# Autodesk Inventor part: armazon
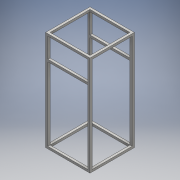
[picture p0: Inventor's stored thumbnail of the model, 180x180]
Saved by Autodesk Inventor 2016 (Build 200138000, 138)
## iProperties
Created: 2016-06
Part Number: armazon
Material: Genérico
Document SubType Name: Modeling
Designer: adm
Density: 1 g/cm^3
Appearance: Valor por defecto
Author: adm
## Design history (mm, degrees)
node "Boceto 3D1"
sketch "Boceto1"
  geometry: L1 (-100, -50)-(-90, -50); L2 (-90, -50)-(-90, -40); L3 (-90, -40)-(-100, -40); L4 (-100, -40)-(-100, -50); L5 (-100, 140)-(-90, 140); L6 (-90, 140)-(-90, 150); L7 (-90, 150)-(-100, 150); L8 (-100, 150)-(-100, 140); L9 (90, 140)-(100, 140); L10 (100, 140)-(100, 150); L11 (100, 150)-(90, 150); L12 (90, 150)-(90, 140); L13 (100, -50)-(100, -40); L14 (90, -50)-(100, -50); L15 (100, -40)-(90, -40); L16 (90, -40)-(90, -50); L17 (-100, -50)-(100, -50); L18 (100, -50)-(100, 150); L19 (100, 150)-(-100, 150); L20 (-100, 150)-(-100, -50); 1 further point
  constraints: 40 end point, 10 parallel, 5 horizontal, 5 perpendicular
  dimensions: "d2" = 10 distance of L3.end L2.end; "d3" = 10 distance of L2.end L1.end; "d4" = 10 distance of L7.end L6.end; "d5" = 10 distance of L6.end L5.end; "d6" = 10 distance of L11.end L10.end; "d7" = 10 distance of L10.end L9.end; "d8" = 10 distance of L15.end L13.end; "d9" = 10 distance of L13.end L13.start; "d47" = 200 distance of L19.end L1.start
extrude "Extrusión1" new body sketch "Boceto1" distance "d10" = 450; taper "d11" = 0 deg
sketch "Boceto2"
  geometry: L1 (0, 0)-(-450, 0) reference; L2 (0, 0)-(-10, 0); L3 (-10, 0)-(-10, 10); L4 (-10, 10)-(0, 10); L5 (0, 10)-(0, 0); 1 further point
  constraints: 8 end point, 2 parallel, 1 horizontal, 1 perpendicular
  dimensions: "d12" = 10 distance of L3.end L4.end; "d13" = 10 distance of L2.end L3.end
extrude "Extrusión2" join sketch "Boceto2" distance "d14" = 180; taper "d15" = 0 deg
sketch "Boceto3"
  geometry: L1 (0, 0)-(-10, 0); L2 (-10, 0)-(-10, 10); L3 (-10, 10)-(0, 10); L4 (0, 10)-(0, 0); 1 further point
  constraints: 8 end point, 2 parallel, 1 horizontal, 1 perpendicular
  dimensions: "d16" = 10 distance of L2.end L3.end; "d17" = 10 distance of L1.end L2.end
extrude "Extrusión3" join sketch "Boceto3" distance "d18" = 180; taper "d19" = 0 deg
sketch "Boceto4"
  geometry: L1 (440, 0)-(0, 0) reference; L2 (0, 0)-(10, 0); L3 (10, 0)-(10, 10); L4 (10, 10)-(0, 10); L5 (0, 10)-(0, 0); L6 (440, 190)-(0, 190) reference; L7 (0, 190)-(10, 190); L8 (10, 190)-(10, 200); L9 (10, 200)-(0, 200); L10 (0, 200)-(0, 190); 1 further point
  constraints: 16 end point, 4 parallel, 2 horizontal, 2 perpendicular
  dimensions: "d20" = 10 distance of L4.end L3.end; "d21" = 10 distance of L3.end L2.end; "d22" = 10 distance of L9.end L8.end; "d23" = 10 distance of L8.end L7.end
extrude "Extrusión4" join sketch "Boceto4" distance "d24" = 180; taper "d25" = 0 deg
sketch "Boceto5"
  geometry: L1 (200, -450)-(200, 0) reference; L2 (10, -440)-(190, -440) reference; L3 (200, -450)-(190, -450); L4 (190, -450)-(190, -440); L5 (190, -440)-(200, -440); L6 (200, -440)-(200, -450); 1 further point
  constraints: 8 end point, 2 parallel, 1 horizontal, 1 perpendicular
  dimensions: "d26" = 10 distance of L2.end L5.end (derived); "d27" = 10 distance of L3.end L2.end (derived)
extrude "Extrusión5" join sketch "Boceto5" distance "d28" = 180; taper "d29" = 0 deg
sketch "Boceto6"
  geometry: L1 (10, -440)-(190, -440) reference; L2 (0, -450)-(10, -450); L3 (10, -450)-(10, -440); L4 (10, -440)-(0, -440); L5 (0, -440)-(0, -450); L6 (0, -450)-(0, 0) reference; L7 (10, -440)-(10, -10) reference; L8 (10, -10)-(190, -10) reference; L9 (0, 0)-(10, 0); L10 (10, 0)-(10, -10); L11 (10, -10)-(0, -10); L12 (0, -10)-(0, 0); L13 (200, 0)-(190, 0); L14 (190, 0)-(190, -10); L15 (190, -10)-(200, -10); L16 (200, -10)-(200, 0); 1 further point
  constraints: 24 end point, 6 parallel, 3 horizontal, 3 perpendicular
  dimensions: "d30" = 10 distance of L4.end L1.start (derived); "d31" = 10 distance of L1.start L2.end (derived); "d32" = 10 distance of L7.end L11.end (derived); "d33" = 10 distance of L9.end L7.end (derived); "d34" = 10 distance of L15.end L8.end (derived); "d35" = 10 distance of L8.end L13.end (derived)
extrude "Extrusión6" join sketch "Boceto6" distance "d36" = 180; taper "d37" = 0 deg
sketch "Boceto7"
  geometry: L1 (-10, 0)-(440, 0) reference; L2 (340, 0)-(330, 0); L3 (330, 0)-(330, 10); L4 (330, 10)-(340, 10); L5 (340, 10)-(340, 0); L6 (340, 190)-(330, 190); L7 (330, 190)-(330, 200); L8 (330, 200)-(340, 200); L9 (340, 200)-(340, 190); L10 (0, 200)-(430, 200) reference; 2 further points
  constraints: 16 end point, 4 parallel, 2 horizontal, 2 perpendicular, 2 point on line
  dimensions: "d38" = 100 distance of L2.start L1.end; "d39" = 10 distance of L3.end L4.end; "d40" = 10 distance of L2.end L3.end; "d41" = 100 horizontal distance of L6.start L1.end; "d42" = 10 distance of L7.end L8.end; "d43" = 10 distance of L6.end L7.end
extrude "Extrusión7" join sketch "Boceto7" distance "d44" = 180; taper "d45" = 0 deg
node "Sólido1"
